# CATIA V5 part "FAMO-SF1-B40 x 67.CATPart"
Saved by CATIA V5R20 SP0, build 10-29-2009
Part number: FAMO-SF1-B40 x 67
Definition: NONE
Nomenclature: FAMO-SF1-B40 x 67
Source: Unknown
Description: FAMO-SF1-B40 x 67
Bounding box of the stored display mesh (mm): x -13 to 54, y -31.5 to 31.5, z -31.5 to 31.5
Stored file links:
  C:\Users\Utente\Desktop\IO LAVORO\3D X SITO CF\X SITO\FAMO\FAMO-SF1-B40 x 67.CATPart
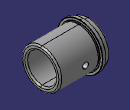
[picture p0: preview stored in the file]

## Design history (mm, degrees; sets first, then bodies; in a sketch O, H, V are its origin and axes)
Body1 "FAMO-SF1-B40 x 67" (main body)
  Solid1: solid without history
